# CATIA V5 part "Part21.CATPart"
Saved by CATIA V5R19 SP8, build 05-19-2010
Part number: Entretoise_c
Bounding box of the stored display mesh (mm): x -51.986 to 51.986, y -51.986 to 51.986, z -326.207 to -261.207
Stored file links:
  G:\EU_thinkMotion\CFAO_2010\MMS_groupe1\MMS_groupe1\OK\ppiault\piault\piault_cfao\Part21.CATPart
  D:\Catia\Finaltest.CATProduct
  G:\Catia Projet\CFAO2\Product2.CATProduct
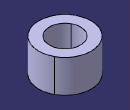
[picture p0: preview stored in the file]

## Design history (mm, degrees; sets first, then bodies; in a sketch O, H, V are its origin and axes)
External parameters (linked from other documents)
  External.LongueurEntretoise = 130 mm
Body1 (main body)
  Sketch1 on zx-plane, origin (0, 0, 0), H (-1, 0, 0), V (0, 0, 1)
    line L1 (-52, -261.2065) -> (-31, -261.2065)
    line L2 (-31, -261.2065) -> (-31, -326.2065)
    line L3 (-31, -326.2065) -> (-52, -326.2065)
    line L4 (-52, -326.2065) -> (-52, -261.2065)
    distance V L2 = 31
    distance V L4 = 52
    distance L1 L3 = 65 {= External.LongueurEntretoise /2}
    horizontal: L1 H, L3 H
    vertical: L2 V, L4 V
  Shaft1: profile Sketch1, axis Sketch1.V, angle 360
